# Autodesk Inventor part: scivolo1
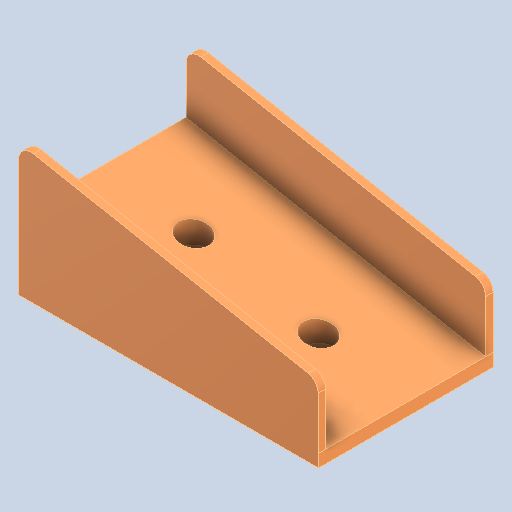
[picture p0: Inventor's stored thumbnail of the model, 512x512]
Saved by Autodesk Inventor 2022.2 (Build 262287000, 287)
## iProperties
Created: 2024-10
Part Number: scivolo1
Material: Alluminio 6061
Document SubType Name: Modeling
Designer: 18907419
Density: 2.7 g/cm^3
Appearance: Default
Author: 18907419
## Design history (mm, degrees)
feature "Solido1"
node "Solido2"
